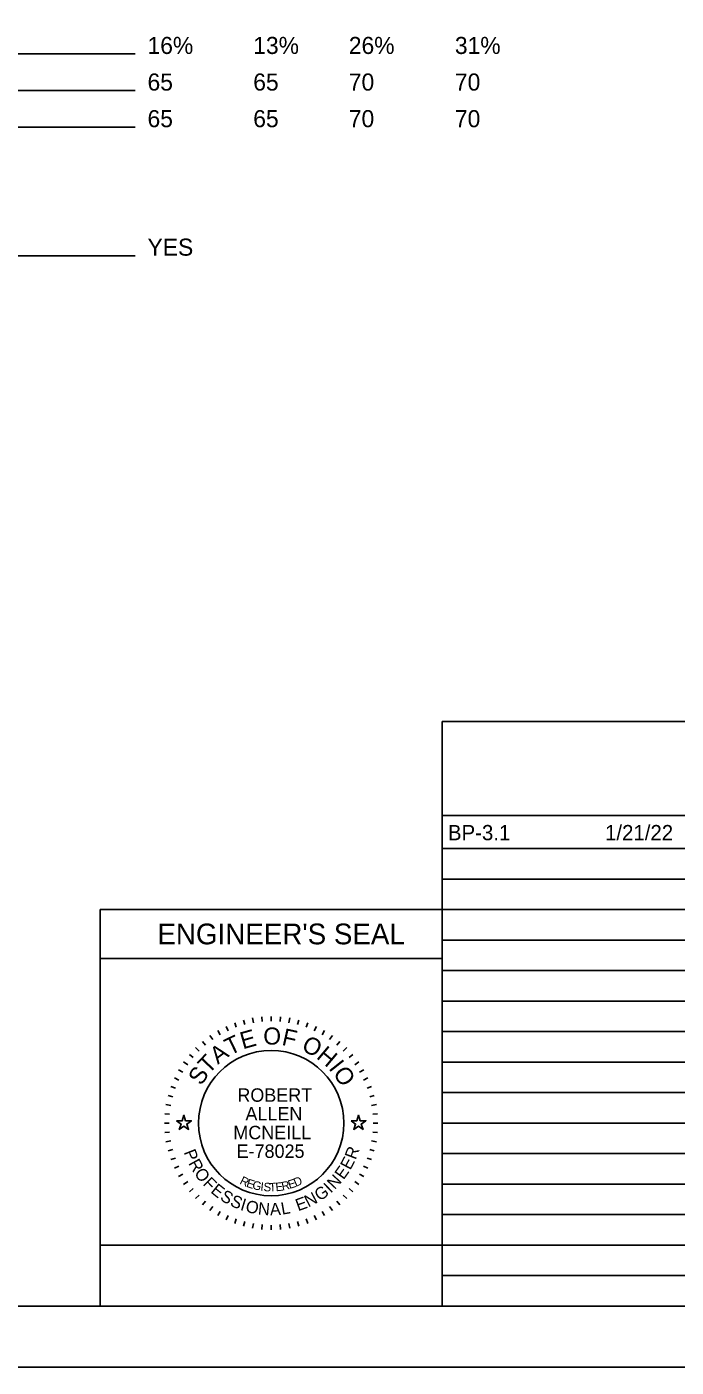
# Model space of a CAD drawing. Extents: x 0 to 34, y 0 to 22.
# Drawn here: x 6.75 to 12.07, y 0 to 10.98 of the extents above; entities that cross this region are included whole.
import ezdxf

# ---------------------------------------------------------------- set-up
doc = ezdxf.new("R2010")
doc.units = 0
for name, color, linetype in [('Default', 7, 'Continuous'), ('SH_Border', 7, 'Continuous'), ('SH_Cut_Line', 7, 'Continuous'), ('SH_Data', 7, 'Continuous'), ('SH_Text', 7, 'Continuous')]:
    doc.layers.add(name, color=color, linetype=linetype)

msp = doc.modelspace()

# ---------------------------------------------------------------- linework, layer by layer
at = {"layer": 'Default'}
for points in [[(7.974, 2.02), (8.021, 2.02), (8.035, 2.065), (8.049, 2.02), (8.096, 2.02), (8.058, 1.992), (8.073, 1.948), (8.035, 1.975), (7.997, 1.948), (8.012, 1.992)], [(9.404, 2.02), (9.451, 2.02), (9.465, 2.065), (9.479, 2.02), (9.526, 2.02), (9.488, 1.992), (9.503, 1.948), (9.465, 1.975), (9.427, 1.948), (9.442, 1.992)]]:
    msp.add_lwpolyline(points, close=True, dxfattribs=at)
at = {"layer": 'SH_Border'}
msp.add_lwpolyline([(1.5, 21.5), (33.5, 21.5), (33.5, 0.5), (1.5, 0.5)], close=True, dxfattribs=at)
at = {"layer": 'SH_Cut_Line'}
msp.add_lwpolyline([(0, 0), (34, 0), (34, 22), (0, 22)], close=True, dxfattribs=at)
at = {"layer": 'SH_Data'}
for p, q in [((7.637, 10.761), (4.189, 10.761)), ((7.637, 10.461), (3.346, 10.461)), ((7.637, 10.161), (3.242, 10.161)), ((7.637, 9.108), (3.267, 9.108)), ((10.15, 5.292), (23.6, 5.292)), ((10.15, 0.5), (10.15, 5.292)), ((10.15, 4.521), (23.6, 4.521)), ((10.15, 4.25), (23.6, 4.25)), ((10.15, 4), (23.6, 4)), ((10.15, 3.75), (7.35, 3.75)), ((7.35, 3.75), (7.35, 0.5)), ((10.15, 3.75), (23.6, 3.75)), ((10.15, 0.5), (10.15, 3.75)), ((10.15, 3.5), (23.6, 3.5)), ((10.15, 3.35), (7.35, 3.35)), ((10.15, 3.25), (23.6, 3.25)), ((10.15, 3), (23.6, 3)), ((8.598, 2.862), (8.605, 2.822)), ((8.674, 2.872), (8.677, 2.832)), ((8.75, 2.875), (8.75, 2.835)), ((8.826, 2.872), (8.823, 2.832)), ((8.902, 2.862), (8.895, 2.822)), ((8.313, 2.758), (8.333, 2.723)), ((8.38, 2.793), (8.397, 2.757)), ((8.451, 2.822), (8.464, 2.785)), ((8.524, 2.845), (8.534, 2.807)), ((8.976, 2.845), (8.966, 2.807)), ((9.049, 2.822), (9.036, 2.785)), ((9.12, 2.793), (9.103, 2.757)), ((9.187, 2.758), (9.167, 2.723)), ((10.15, 2.75), (23.6, 2.75)), ((8.188, 2.67), (8.213, 2.64)), ((8.248, 2.717), (8.271, 2.684)), ((9.252, 2.717), (9.229, 2.684)), ((9.312, 2.67), (9.287, 2.64)), ((8.08, 2.562), (8.11, 2.537)), ((8.131, 2.619), (8.16, 2.59)), ((9.369, 2.619), (9.34, 2.59)), ((9.42, 2.562), (9.39, 2.537)), ((7.992, 2.438), (8.027, 2.418)), ((8.033, 2.502), (8.066, 2.479)), ((9.467, 2.502), (9.434, 2.479)), ((9.508, 2.438), (9.473, 2.418)), ((10.15, 2.5), (23.6, 2.5)), ((7.957, 2.37), (7.993, 2.353)), ((9.543, 2.37), (9.507, 2.353)), ((7.905, 2.226), (7.943, 2.216)), ((7.928, 2.299), (7.965, 2.286)), ((9.572, 2.299), (9.535, 2.286)), ((9.595, 2.226), (9.557, 2.216)), ((10.15, 2.25), (23.6, 2.25)), ((7.888, 2.152), (7.928, 2.145)), ((9.612, 2.152), (9.572, 2.145)), ((7.875, 2), (7.915, 2)), ((7.878, 2.076), (7.918, 2.073)), ((9.622, 2.076), (9.582, 2.073)), ((9.625, 2), (9.585, 2)), ((10.15, 2), (23.6, 2)), ((7.878, 1.924), (7.918, 1.927)), ((9.622, 1.924), (9.582, 1.927)), ((7.888, 1.848), (7.928, 1.855)), ((7.905, 1.774), (7.943, 1.784)), ((9.595, 1.774), (9.557, 1.784)), ((9.612, 1.848), (9.572, 1.855)), ((7.928, 1.701), (7.965, 1.714)), ((9.572, 1.701), (9.535, 1.714)), ((10.15, 1.75), (23.6, 1.75)), ((7.957, 1.63), (7.993, 1.647)), ((7.992, 1.563), (8.027, 1.583)), ((9.508, 1.563), (9.473, 1.583)), ((9.543, 1.63), (9.507, 1.647)), ((8.033, 1.498), (8.066, 1.521)), ((8.08, 1.438), (8.11, 1.463)), ((9.42, 1.438), (9.39, 1.463)), ((9.467, 1.498), (9.434, 1.521)), ((10.15, 1.5), (23.6, 1.5)), ((8.131, 1.381), (8.16, 1.41)), ((8.188, 1.33), (8.213, 1.36)), ((9.312, 1.33), (9.287, 1.36)), ((9.369, 1.381), (9.34, 1.41)), ((8.248, 1.283), (8.271, 1.316)), ((8.313, 1.242), (8.333, 1.277)), ((8.38, 1.207), (8.397, 1.243)), ((8.451, 1.178), (8.464, 1.215)), ((9.049, 1.178), (9.036, 1.215)), ((9.12, 1.207), (9.103, 1.243)), ((9.187, 1.242), (9.167, 1.277)), ((9.252, 1.283), (9.229, 1.316)), ((10.15, 1.25), (23.6, 1.25)), ((8.524, 1.155), (8.534, 1.193)), ((8.598, 1.138), (8.605, 1.178)), ((8.674, 1.128), (8.677, 1.168)), ((8.75, 1.125), (8.75, 1.165)), ((8.826, 1.128), (8.823, 1.168)), ((8.902, 1.138), (8.895, 1.178)), ((8.976, 1.155), (8.966, 1.193)), ((10.15, 1), (23.6, 1)), ((10.15, 0.75), (23.6, 0.75)), ((10.15, 0.5), (7.35, 0.5))]:
    msp.add_line(p, q, dxfattribs=at)
msp.add_lwpolyline([(10.15, 0.5), (10.15, 1), (7.35, 1), (7.35, 0.5)], close=True, dxfattribs=at)
msp.add_circle((8.75, 2), 0.595, dxfattribs=at)

# ---------------------------------------------------------------- texts
at = {"layer": 'Default'}
for s, p in [('BP-3.1', (10.198, 4.318)), ('1/21/22', (11.485, 4.318))]:
    msp.add_text(s, height=0.125, dxfattribs=at).set_placement(p)
at = {"layer": 'SH_Data'}
for s, height, p in [("ENGINEER'S SEAL", 0.17, (7.818, 3.465)), ('ROBERT', 0.11, (8.473, 2.175)), ('ALLEN', 0.11, (8.539, 2.022)), ('MCNEILL', 0.11, (8.44, 1.868)), ('E-78025', 0.11, (8.467, 1.715))]:
    msp.add_text(s, height=height, dxfattribs=at).set_placement(p)
for s, height, rotation, p in [('E', 0.14, 15.7571, (8.518, 2.604)), ('O', 0.14, 359.7812, (8.685, 2.644)), ('F', 0.14, 347.4362, (8.831, 2.642)), ('T', 0.14, 25.7167, (8.412, 2.552)), ('O', 0.14, 332.2586, (8.99, 2.602)), ('T', 0.14, 46.4344, (8.238, 2.396)), ('A', 0.14, 36.4747, (8.313, 2.478)), ('H', 0.14, 319.9136, (9.113, 2.536)), ('S', 0.14, 57.1924, (8.178, 2.301)), ('I', 0.14, 308.367, (9.216, 2.448)), ('O', 0.14, 303.1491, (9.252, 2.409)), ('P', 0.1, 291.494, (8.032, 1.762)), ('R', 0.1, 69.2322, (9.442, 1.695)), ('R', 0.1, 298.7311, (8.069, 1.672)), ('E', 0.1, 54.758, (9.343, 1.531)), ('E', 0.1, 61.9951, (9.398, 1.61)), ('O', 0.1, 306.4666, (8.115, 1.588)), ('F', 0.1, 314.7068, (8.184, 1.498)), ('R', 0.07, 334.487, (8.487, 1.505)), ('E', 0.07, 341.04, (8.541, 1.48)), ('E', 0.07, 17.6836, (8.9, 1.46)), ('D', 0.07, 23.3052, (8.951, 1.477)), ('N', 0.1, 47.0224, (9.27, 1.451)), ('E', 0.1, 321.4393, (8.248, 1.435)), ('S', 0.1, 328.6764, (8.324, 1.375)), ('G', 0.07, 347.4752, (8.591, 1.462)), ('I', 0.07, 353.7858, (8.659, 1.447)), ('S', 0.07, 356.8926, (8.686, 1.443)), ('T', 0.07, 3.0061, (8.736, 1.439)), ('E', 0.07, 6.0117, (8.789, 1.441)), ('R', 0.07, 11.9184, (8.842, 1.447)), ('N', 0.1, 27.3113, (9.054, 1.308)), ('G', 0.1, 35.0469, (9.148, 1.357)), ('I', 0.1, 43.287, (9.237, 1.421)), ('S', 0.1, 335.9134, (8.406, 1.327)), ('I', 0.1, 343.1505, (8.491, 1.29)), ('O', 0.1, 346.8859, (8.534, 1.275)), ('N', 0.1, 355.1261, (8.639, 1.252)), ('A', 0.1, 2.8617, (8.742, 1.244)), ('L', 0.1, 10.0987, (8.839, 1.249)), ('E', 0.1, 20.0742, (8.971, 1.277))]:
    msp.add_text(s, height=height, rotation=rotation, dxfattribs=at).set_placement(p)
at = {"layer": 'SH_Text'}
for s, p in [('16%', (7.737, 10.761)), ('13%', (8.603, 10.761)), ('26%', (9.386, 10.761)), ('31%', (10.255, 10.761)), ('65', (7.737, 10.461)), ('65', (8.603, 10.461)), ('70', (9.386, 10.461)), ('70', (10.255, 10.461)), ('65', (7.737, 10.161)), ('65', (8.603, 10.161)), ('70', (9.386, 10.161)), ('70', (10.255, 10.161)), ('YES', (7.737, 9.108))]:
    msp.add_text(s, height=0.14, dxfattribs=at).set_placement(p)

doc.saveas('drawing.dxf')
